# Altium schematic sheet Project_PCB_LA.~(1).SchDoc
size A4
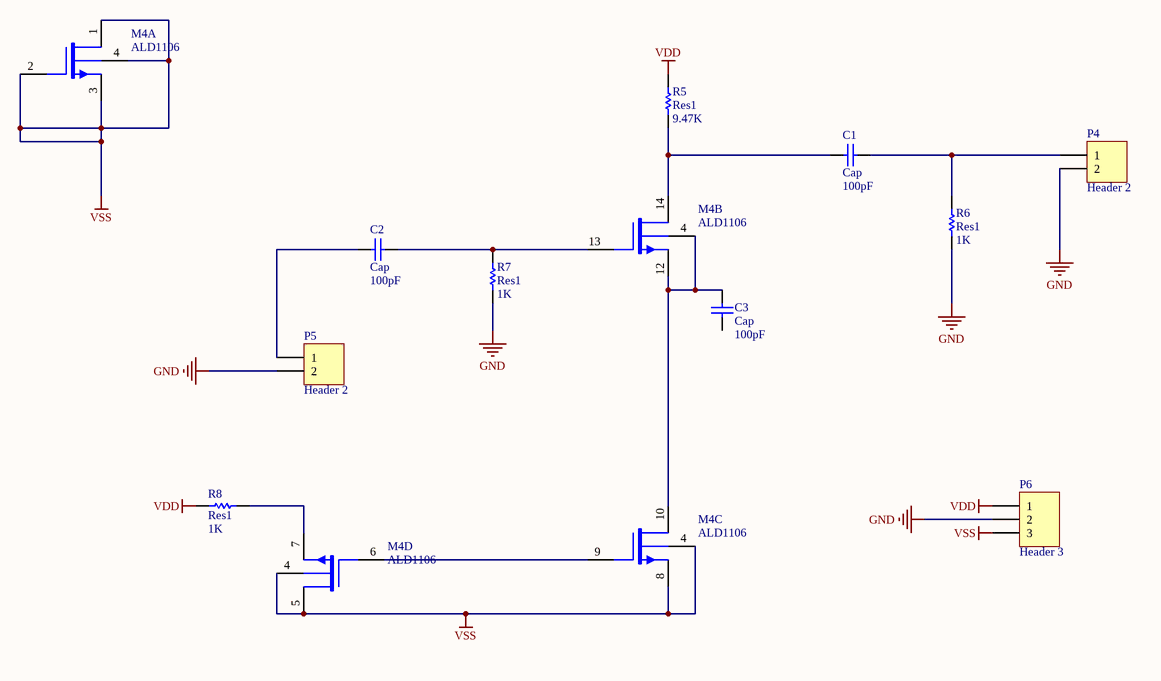
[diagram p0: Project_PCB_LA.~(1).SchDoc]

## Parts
C1  Cap  value 100pF  [RAD-0.3]
C2  Cap  value 100pF  [RAD-0.3]
C3  Cap  value 100pF  [RAD-0.3]
M4  ALD1106  [DIP-14]  (parts A,B,C,D of 4)
P4  Header 2  [HDR1X2]
P5  Header 2  [HDR1X2]
P6  Header 3  [HDR1X3]
R5  Res1  value 9.47K  [AXIAL-0.3]
R6  Res1  value 1K  [AXIAL-0.3]
R7  Res1  value 1K  [AXIAL-0.3]
R8  Res1  value 1K  [AXIAL-0.3]

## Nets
GND: P4.2 P5.2 P6.2 R6.1 R7.1
VDD: P6.1 R5.2 R8.1
VSS: M4.1(DN1) M4.2(GN1) M4.3(SN1) M4.4(V-) M4.5(DN4) M4.8(SN3) P6.3
NetC1_1: C1.1 M4.14(DN2) R5.1
NetC1_2: C1.2 P4.1 R6.2
NetC2_1: C2.1 P5.1
NetC2_2: C2.2 M4.13(GN2) R7.2
NetC3_1: C3.1 M4.4(V-) M4.10(DN3) M4.12(SN2)
NetM4_6: M4.6(GN4) M4.9(GN3)
NetM4_7: M4.7(SN4) R8.2

Not connected (* = marked no-connect by the designer): C3 2

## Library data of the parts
C1-C3 = Cap: Capacitor
M4 = ALD1106: Quad N-channel matched MOSFET array
P4 P5 = Header 2: Header, 2-Pin
P6 = Header 3: Header, 3-Pin
R5-R8 = Res1: Resistor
